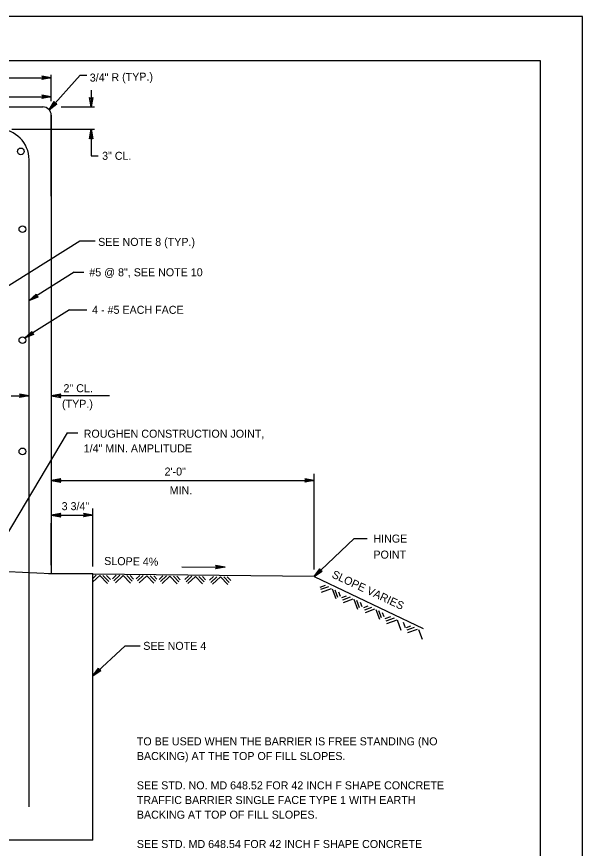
# Model space of a CAD drawing. Extents: x -27.4 to -18.9, y -4.2 to 6.8.
# Drawn here: x -23.16 to -18.92, y 0.57 to 6.81 of the extents above; entities that cross this region are included whole.
import ezdxf

# ---------------------------------------------------------------- set-up
doc = ezdxf.new("R2010")
doc.units = 0
for name, color, linetype in [('BORD-LINE', 7, 'Continuous'), ('DETL-DIMS', 7, 'Continuous'), ('DETL-NOTE', 7, 'Continuous'), ('Level 1', 7, 'Continuous'), ('Level 10', 7, 'Continuous'), ('Level 12', 7, 'Continuous'), ('Level 6', 7, 'Continuous'), ('SECT-GRND_P', 7, 'Continuous'), ('SUBS-FOOT_P', 7, 'Continuous'), ('SUPR-PARA_P', 7, 'Continuous'), ('SUPR-RFRC', 7, 'Continuous'), ('USER-CLIP', 7, 'Continuous')]:
    doc.layers.add(name, color=color, linetype=linetype)

msp = doc.modelspace()

# ---------------------------------------------------------------- linework, layer by layer
at = {"layer": 'BORD-LINE'}
msp.add_lwpolyline([(-26.6066, 6.4791), (-19.2324, 6.4791), (-19.2324, -3.874), (-26.6066, -3.874)], close=True, dxfattribs=at)
at = {"layer": 'DETL-DIMS'}
for p, q in [((-22.8998, 6.3507), (-22.9713, 6.3632)), ((-22.9713, 6.3632), (-22.9578, 6.3507)), ((-22.8998, 6.3507), (-22.9713, 6.338)), ((-22.9578, 6.3507), (-22.9713, 6.338)), ((-22.8998, 6.2075), (-22.9713, 6.22)), ((-22.9713, 6.22), (-22.9578, 6.2075)), ((-22.8998, 6.2075), (-22.9713, 6.1948)), ((-22.9578, 6.2075), (-22.9713, 6.1948)), ((-22.5998, 6.132), (-22.6125, 6.2035)), ((-22.5998, 6.19), (-22.6125, 6.2035)), ((-22.5998, 6.132), (-22.5873, 6.2035)), ((-22.5873, 6.2035), (-22.5998, 6.19)), ((-22.9154, 6.1108), (-22.8773, 6.1727)), ((-22.9154, 6.1108), (-22.8585, 6.1559)), ((-22.8768, 6.1541), (-22.8773, 6.1727)), ((-22.8585, 6.1559), (-22.8768, 6.1541)), ((-22.5998, 5.9653), (-22.6123, 5.8939)), ((-22.5998, 5.9653), (-22.5871, 5.8938)), ((-22.6123, 5.8939), (-22.5998, 5.9073)), ((-22.5998, 5.9073), (-22.5871, 5.8938)), ((-23.0665, 4.6801), (-23.0127, 4.7289)), ((-23.0665, 4.6801), (-22.9993, 4.7075)), ((-23.0174, 4.7109), (-23.0127, 4.7289)), ((-22.9993, 4.7075), (-23.0174, 4.7109)), ((-23.0988, 4.3996), (-23.045, 4.4484)), ((-23.0497, 4.4305), (-23.045, 4.4484)), ((-23.0316, 4.427), (-23.0497, 4.4305)), ((-23.0988, 4.3996), (-23.0316, 4.427)), ((-23.0665, 3.9653), (-23.138, 3.9778)), ((-23.138, 3.9778), (-23.1245, 3.9653)), ((-23.0665, 3.9653), (-23.138, 3.9526)), ((-23.1245, 3.9653), (-23.138, 3.9526)), ((-22.8998, 3.9653), (-22.8283, 3.9778)), ((-22.8998, 3.9653), (-22.8283, 3.9526)), ((-22.8283, 3.9778), (-22.8418, 3.9653)), ((-22.8418, 3.9653), (-22.8283, 3.9526)), ((-22.8998, 3.3301), (-22.8284, 3.3426)), ((-22.8998, 3.3301), (-22.8283, 3.3174)), ((-22.8284, 3.3426), (-22.8418, 3.3301)), ((-22.8418, 3.3301), (-22.8283, 3.3174)), ((-20.9272, 3.3301), (-20.9987, 3.3426)), ((-20.9987, 3.3426), (-20.9852, 3.3301)), ((-20.9272, 3.3301), (-20.9987, 3.3174)), ((-20.9852, 3.3301), (-20.9987, 3.3174)), ((-22.9002, 3.0705), (-22.8287, 3.083)), ((-22.9002, 3.0705), (-22.8287, 3.083)), ((-22.9002, 3.0705), (-22.8287, 3.0578)), ((-22.9002, 3.0705), (-22.8287, 3.0578)), ((-22.8287, 3.083), (-22.8422, 3.0705)), ((-22.8287, 3.083), (-22.8422, 3.0705)), ((-22.8422, 3.0705), (-22.8287, 3.0578)), ((-22.8422, 3.0705), (-22.8287, 3.0578)), ((-22.587, 3.0705), (-22.6585, 3.083)), ((-22.6585, 3.083), (-22.645, 3.0705)), ((-22.587, 3.0705), (-22.6585, 3.083)), ((-22.6585, 3.083), (-22.645, 3.0705)), ((-22.587, 3.0705), (-22.6585, 3.0578)), ((-22.645, 3.0705), (-22.6585, 3.0578)), ((-22.587, 3.0705), (-22.6585, 3.0578)), ((-22.645, 3.0705), (-22.6585, 3.0578)), ((-21.5964, 2.6798), (-21.6677, 2.6932)), ((-21.6677, 2.6932), (-21.6544, 2.6805)), ((-21.6544, 2.6805), (-21.668, 2.668)), ((-21.5964, 2.6798), (-21.668, 2.668)), ((-20.9275, 2.6095), (-20.8841, 2.6676)), ((-20.9275, 2.6095), (-20.8668, 2.6493)), ((-20.8841, 2.6676), (-20.8853, 2.6493)), ((-20.8853, 2.6493), (-20.8668, 2.6493)), ((-22.588, 1.8646), (-22.5443, 1.9227)), ((-22.588, 1.8646), (-22.5271, 1.9042)), ((-22.5455, 1.9042), (-22.5443, 1.9227)), ((-22.5271, 1.9042), (-22.5455, 1.9042))]:
    msp.add_line(p, q, dxfattribs=at)
for points in [[(-22.9713, 6.3632), (-22.8998, 6.3507), (-22.9713, 6.338), (-22.9578, 6.3507)], [(-22.9713, 6.22), (-22.8998, 6.2075), (-22.9713, 6.1948), (-22.9578, 6.2075)], [(-22.5873, 6.2035), (-22.5998, 6.132), (-22.6125, 6.2035), (-22.5998, 6.19)], [(-22.8585, 6.1559), (-22.9154, 6.1108), (-22.8773, 6.1727), (-22.8768, 6.1541)], [(-22.6123, 5.8939), (-22.5998, 5.9653), (-22.5871, 5.8938), (-22.5998, 5.9073)], [(-22.9993, 4.7075), (-23.0665, 4.6801), (-23.0127, 4.7289), (-23.0174, 4.7109)], [(-23.0316, 4.427), (-23.0988, 4.3996), (-23.045, 4.4484), (-23.0497, 4.4305)], [(-23.138, 3.9778), (-23.0665, 3.9653), (-23.138, 3.9526), (-23.1245, 3.9653)], [(-22.8283, 3.9778), (-22.8998, 3.9653), (-22.8283, 3.9526), (-22.8418, 3.9653)], [(-22.8284, 3.3426), (-22.8998, 3.3301), (-22.8283, 3.3174), (-22.8418, 3.3301)], [(-20.9987, 3.3426), (-20.9272, 3.3301), (-20.9987, 3.3174), (-20.9852, 3.3301)], [(-22.8287, 3.083), (-22.9002, 3.0705), (-22.8287, 3.0578), (-22.8422, 3.0705)], [(-22.8287, 3.083), (-22.9002, 3.0705), (-22.8287, 3.0578), (-22.8422, 3.0705)], [(-22.6585, 3.083), (-22.587, 3.0705), (-22.6585, 3.0578), (-22.645, 3.0705)], [(-22.6585, 3.083), (-22.587, 3.0705), (-22.6585, 3.0578), (-22.645, 3.0705)], [(-21.6677, 2.6932), (-21.5964, 2.6798), (-21.668, 2.668), (-21.6544, 2.6805)], [(-20.8841, 2.6676), (-20.9275, 2.6095), (-20.8668, 2.6493), (-20.8853, 2.6493)], [(-22.5271, 1.9042), (-22.588, 1.8646), (-22.5443, 1.9227), (-22.5455, 1.9042)]]:
    msp.add_lwpolyline(points, close=True, dxfattribs=at)
at = {"layer": 'Level 1'}
msp.add_line((-22.8998, 6.0695), (-22.8998, 2.632), dxfattribs=at)
at = {"layer": 'Level 10'}
for p, q in [((-22.6832, 6.3713), (-22.9154, 6.1108)), ((-22.8998, 6.1751), (-22.8998, 6.3715)), ((-22.6832, 6.3713), (-22.6318, 6.3713)), ((-24.4207, 6.3507), (-22.8998, 6.3507)), ((-22.5998, 6.257), (-22.5998, 6.132)), ((-23.7366, 6.2075), (-22.8998, 6.2075)), ((-22.8267, 6.132), (-22.5748, 6.132)), ((-22.8998, 5.4624), (-22.8998, 6.076)), ((-23.1957, 5.9653), (-22.5748, 5.9653)), ((-22.5998, 5.9653), (-22.5998, 5.7653)), ((-22.5998, 5.7653), (-22.5485, 5.7653)), ((-22.6858, 5.1263), (-23.3681, 4.6984)), ((-22.6856, 5.1275), (-22.5711, 5.1275)), ((-22.7287, 4.8919), (-23.0665, 4.6801)), ((-22.7287, 4.8919), (-22.6543, 4.8919)), ((-22.7628, 4.6103), (-23.0988, 4.3996)), ((-22.7628, 4.6103), (-22.6335, 4.6103)), ((-23.2017, 3.9653), (-23.0665, 3.9653)), ((-22.4632, 3.9653), (-22.8998, 3.9653)), ((-22.7813, 3.6866), (-23.4246, 2.6127)), ((-22.7813, 3.6866), (-22.7013, 3.6866)), ((-20.9273, 2.6617), (-20.9273, 3.3801)), ((-22.8998, 3.3301), (-20.9275, 3.3301)), ((-22.5872, 2.6843), (-22.5872, 3.1205)), ((-22.8998, 3.0705), (-22.5873, 3.0705)), ((-22.8998, 2.6945), (-22.8998, 3.0112)), ((-20.6265, 2.8949), (-20.9273, 2.6094)), ((-20.6265, 2.8949), (-20.5306, 2.8949)), ((-21.9208, 2.6835), (-21.5965, 2.6798)), ((-22.588, 1.8646), (-22.3462, 2.09)), ((-22.3462, 2.09), (-22.2335, 2.09))]:
    msp.add_line(p, q, dxfattribs=at)
at = {"layer": 'Level 6'}
for p, q in [((-22.5619, 2.6203), (-22.588, 2.5958)), ((-22.588, 2.5694), (-22.5354, 2.6188)), ((-22.5354, 2.6188), (-22.4787, 2.5583)), ((-22.469, 2.5728), (-22.512, 2.6188)), ((-22.4842, 2.6179), (-22.4565, 2.5883)), ((-22.4413, 2.5923), (-22.4119, 2.6197)), ((-22.3859, 2.6193), (-22.4311, 2.5768)), ((-22.4185, 2.5639), (-22.3599, 2.6189)), ((-22.3599, 2.6189), (-22.3045, 2.5602)), ((-22.293, 2.5752), (-22.3339, 2.6186)), ((-22.3079, 2.6182), (-22.2823, 2.591)), ((-22.2622, 2.5919), (-22.2354, 2.6172)), ((-22.2094, 2.6168), (-22.2523, 2.5766)), ((-22.2396, 2.5636), (-22.1834, 2.6164)), ((-22.1834, 2.6164), (-22.1303, 2.56)), ((-22.1186, 2.575), (-22.1574, 2.616)), ((-22.1314, 2.6157), (-22.1079, 2.5908)), ((-22.091, 2.5873), (-22.0616, 2.6147)), ((-22.0356, 2.6143), (-22.081, 2.5718)), ((-22.0684, 2.5589), (-22.0096, 2.6139)), ((-22.0096, 2.6139), (-21.9544, 2.5551)), ((-21.9427, 2.5701), (-21.9836, 2.6136)), ((-21.9576, 2.6132), (-21.932, 2.586)), ((-21.8971, 2.5867), (-21.8701, 2.6119)), ((-21.8441, 2.6116), (-21.8872, 2.5713)), ((-21.8745, 2.5583), (-21.8181, 2.6112)), ((-21.8181, 2.6112), (-21.7651, 2.5548)), ((-21.7533, 2.5698), (-21.7921, 2.6108)), ((-21.7661, 2.6104), (-21.7428, 2.5856)), ((-21.7128, 2.5818), (-21.6834, 2.6093)), ((-21.6574, 2.6089), (-21.7029, 2.5664)), ((-21.6902, 2.5535), (-21.6314, 2.6085)), ((-21.6314, 2.6085), (-21.5763, 2.5497)), ((-21.5646, 2.5647), (-21.6054, 2.6081)), ((-21.5794, 2.6078), (-21.5538, 2.5806)), ((-20.8835, 2.5309), (-20.8423, 2.5459)), ((-20.8212, 2.5327), (-20.879, 2.5117)), ((-20.8715, 2.4939), (-20.7987, 2.5204)), ((-20.792, 2.5174), (-20.7655, 2.4442)), ((-20.7508, 2.4539), (-20.7703, 2.5071)), ((-20.745, 2.4952), (-20.7333, 2.4631)), ((-20.7203, 2.4531), (-20.6838, 2.4664)), ((-20.6585, 2.4546), (-20.7158, 2.4337)), ((-20.7083, 2.4161), (-20.634, 2.4429)), ((-20.6295, 2.4407), (-20.6023, 2.3664)), ((-20.5875, 2.3759), (-20.6075, 2.4304)), ((-20.5823, 2.4186), (-20.57, 2.3851)), ((-20.5557, 2.3781), (-20.522, 2.3902)), ((-20.497, 2.3784), (-20.5512, 2.3587)), ((-20.5437, 2.3411), (-20.4723, 2.3669)), ((-20.4637, 2.3627), (-20.4377, 2.2914)), ((-20.423, 2.3009), (-20.4418, 2.3526)), ((-20.4165, 2.3407), (-20.4053, 2.3102)), ((-20.3952, 2.2944), (-20.3518, 2.3102)), ((-20.3265, 2.2984), (-20.3907, 2.2752)), ((-20.383, 2.2572), (-20.3055, 2.2856)), ((-20.3055, 2.2856), (-20.2772, 2.2077)), ((-20.2597, 2.2667), (-20.2448, 2.2266)), ((-20.2358, 2.2271), (-20.2017, 2.2396)), ((-20.1765, 2.2276), (-20.2312, 2.2077)), ((-20.2237, 2.1901), (-20.152, 2.2162)), ((-20.144, 2.2124), (-20.1178, 2.1404))]:
    msp.add_line(p, q, dxfattribs=at)
at = {"layer": 'SECT-GRND_P'}
for q in [(-22.588, 2.6282), (-20.1109, 2.2205)]:
    msp.add_line((-20.9273, 2.6094), q, dxfattribs=at)
at = {"layer": 'SUBS-FOOT_P'}
for p, q in [((-23.2225, 2.648), (-22.8998, 2.632)), ((-22.9207, 2.632), (-22.5873, 2.632)), ((-22.588, 0.632), (-22.588, 2.632)), ((-22.588, 0.632), (-24.9207, 0.632))]:
    msp.add_line(p, q, dxfattribs=at)
at = {"layer": 'SUPR-PARA_P'}
for p, q in [((-23.6803, 6.132), (-22.9613, 6.132)), ((-22.8998, 6.0695), (-22.8998, 2.632))]:
    msp.add_line(p, q, dxfattribs=at)
msp.add_arc((-22.9623, 6.0695), 0.0625, 0, 90, dxfattribs=at)
at = {"layer": 'SUPR-RFRC'}
msp.add_line((-23.0665, 0.882), (-23.0665, 5.7362), dxfattribs=at)
for centre in [(-23.1278, 5.7987), (-23.1165, 5.2153), (-23.1165, 4.382), (-23.1165, 3.5486)]:
    msp.add_circle(centre, 0.025, dxfattribs=at)
msp.add_arc((-23.2957, 5.7362), 0.2292, 0, 90, dxfattribs=at)
at = {"layer": 'USER-CLIP'}
msp.add_lwpolyline([(-18.9155, 6.8091), (-27.4155, 6.8091), (-27.4155, -4.1909), (-18.9155, -4.1909)], close=True, dxfattribs=at)

# ---------------------------------------------------------------- texts
at = {"layer": 'DETL-NOTE'}
msp.add_text('3" CL.', height=0.06001, dxfattribs=at).set_placement((-22.5185, 5.7353))
at = {"layer": 'Level 12'}
for s, rotation, p in [('3/4" R (TYP.)', 1, (-22.6105, 6.3217)), ('SLOPE 4%', 359.17959, (-22.5031, 2.697)), ('SLOPE VARIES', 335, (-20.8008, 2.6052))]:
    msp.add_text(s, height=0.06001, rotation=rotation, dxfattribs=at).set_placement(p)
for s, height, p in [('SEE NOTE 8 (TYP.)', 0.06001, (-22.5481, 5.0897)), ('#5 @ 8", SEE NOTE 10', 0.06001, (-22.6142, 4.8619)), ('4 - #5 EACH FACE', 0.06001, (-22.5934, 4.5803)), ('2" CL.', 0.06001, (-22.8081, 3.9923)), ('(TYP.)', 0.06001, (-22.8192, 3.8753)), ('ROUGHEN CONSTRUCTION JOINT,', 0.06, (-22.6567, 3.6511)), ('1/4" MIN. AMPLITUDE', 0.06, (-22.6567, 3.5411)), ('2\'-0"', 0.06001, (-22.0498, 3.3673)), ('MIN.', 0.06001, (-22.0118, 3.2272)), ('3 3/4"', 0.06001, (-22.8218, 3.1077)), ('HINGE ', 0.06001, (-20.4832, 2.8646)), ('POINT', 0.06001, (-20.4832, 2.7446)), ('SEE NOTE 4', 0.06001, (-22.2097, 2.06)), ('TO BE USED WHEN THE BARRIER IS FREE STANDING (NO ', 0.06, (-22.2579, 1.3439)), ('BACKING) AT THE TOP OF FILL SLOPES. ', 0.06, (-22.2579, 1.2339)), ('SEE STD. NO. MD 648.52 FOR 42 INCH F SHAPE CONCRETE ', 0.06, (-22.2579, 1.0139)), ('TRAFFIC BARRIER SINGLE FACE TYPE 1 WITH EARTH ', 0.06, (-22.2579, 0.9039)), ('BACKING AT TOP OF FILL SLOPES. ', 0.06, (-22.2579, 0.7939)), ('SEE STD. MD 648.54 FOR 42 INCH F SHAPE CONCRETE ', 0.06, (-22.2579, 0.5739))]:
    msp.add_text(s, height=height, dxfattribs=at).set_placement(p)

doc.saveas('drawing.dxf')
